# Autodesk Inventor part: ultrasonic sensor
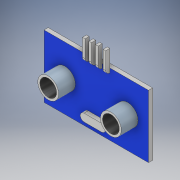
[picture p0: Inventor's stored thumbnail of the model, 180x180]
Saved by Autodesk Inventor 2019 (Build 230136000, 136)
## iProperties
Created: 2021-07
Part Number: ultrasonic sensor
Material: Generic
Document SubType Name: Modeling
Designer: Avinash
Density: 1 g/cm^3
Appearance: Default
Author: Avinash
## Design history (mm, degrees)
sketch "Sketch1"
  geometry: L1 (0, 0)-(-50, 0); L2 (-50, 0)-(-50, 30); L3 (-50, 30)-(0, 30); L4 (0, 30)-(0, 0)
  constraints: 8 end point, 2 parallel, 1 horizontal, 1 perpendicular
  dimensions: "d0" = 50 distance of L2.end L3.end; "d1" = 30 distance of L1.end L2.end
extrude "Extrusion1" new body sketch "Sketch1" distance "d2" = 2; taper "d3" = 0 deg
sketch "Sketch2"
  geometry: L1 (-50, 30)-(-50, 0) reference; L2 (0, 0)-(0, 30) reference; L3 (0, 30)-(-50, 30) reference; C1 r 5 at (-10, 15); C2 r 5 at (-40, 15); C3 r 4 at (-40, 15); C4 r 4 at (-10, 15)
  constraints: 4 centre point
  dimensions: "d4" = 10 diameter of C1; "d5" = 10 diameter of C2; "d6" = 10 distance from line of L1 C2.centre; "d7" = 10 distance from line of L2 C1.centre; "d8" = 15 distance from line of L3 C1.centre; "d9" = 15 distance from line of L3 C2.centre; "d12" = 1 radial gap between concentric circles of C1 C4
extrude "Extrusion3" join sketch "Sketch2" distance "d13" = 8; taper "d14" = 0 deg
sketch "Sketch3"
  geometry: C1 r 1.5 at (29.764, 0); C2 r 1.5 at (0, 0); 1 further point
  constraints: 2 centre point
  dimensions: "d15" = 3 diameter of C2; "d16" = 3 diameter of C1
extrude "Extrusion4" join sketch "Sketch3" distance "d17" = 2; taper "d18" = 0 deg
sketch "Sketch4"
  geometry: L1 (-20.479, 5.269)-(-28.83, 5.269); L2 (-20.479, 7.102)-(-28.83, 7.102); L3 (-28.83, 3.436)-(-20.479, 3.436); A1 r 1.833 centre (-20.479, 5.269) between (-20.479, 3.436) and (-20.479, 7.102); A2 r 1.833 centre (-28.83, 5.269) between (-28.83, 7.102) and (-28.83, 3.436); 2 further points
  constraints: 8 end point, 4 point on circle, 4 tangent, 2 centre point, 1 horizontal, 1 midpoint, 1 parallel
extrude "Extrusion5" join sketch "Sketch4" distance "d19" = 2; taper "d20" = 0 deg
sketch "Sketch5"
  geometry: L1 (-18.495, 27.951)-(-19.753, 27.951); L2 (-19.753, 27.951)-(-19.753, 38.125); L3 (-19.753, 38.125)-(-18.495, 38.125); L4 (-18.495, 38.125)-(-18.495, 27.951); L5 (-22.132, 28.067)-(-23.391, 28.067); L6 (-23.391, 28.067)-(-23.391, 38.241); L7 (-23.391, 38.241)-(-22.132, 38.241); L8 (-22.132, 38.241)-(-22.132, 28.067); L9 (-25.239, 27.963)-(-26.498, 27.963); L10 (-26.498, 27.963)-(-26.498, 38.137); L11 (-26.498, 38.137)-(-25.239, 38.137); L12 (-25.239, 38.137)-(-25.239, 27.963); L13 (-28.391, 27.948)-(-29.649, 27.948); L14 (-29.649, 27.948)-(-29.649, 38.121); L15 (-29.649, 38.121)-(-28.391, 38.121); L16 (-28.391, 38.121)-(-28.391, 27.948); 1 further point
  constraints: 32 end point, 8 parallel, 4 horizontal, 4 perpendicular
  dimensions: "d21" = 1.25861 distance of L1.start L1.end; "d22" = 10.1738 distance of L1.end L2.end; "d23" = 1.25861 distance of L5.start L5.end; "d24" = 10.1738 distance of L5.end L6.end; "d25" = 1.25861 distance of L9.start L9.end; "d26" = 10.1738 distance of L9.end L10.end; "d27" = 1.25861 distance of L13.start L13.end; "d28" = 10.1738 distance of L13.end L14.end
extrude "Extrusion6" join sketch "Sketch5" distance "d29" = 2; taper "d30" = 0 deg
fillet "Fillet1" dims "d31" = 2
fillet "Fillet2" dims "d32" = 2
body "Solid1"
